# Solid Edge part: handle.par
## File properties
Title: Handle
Author: Robert a Rhodes jr
Template: Normal.par
Last saved by: Cadcim
Revision: 6
Application: Solid Edge
Material: aluminum
Accuracy: 0.99
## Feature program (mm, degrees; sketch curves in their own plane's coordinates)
sketch for "unnamed RevolvedProtrusion 1" plane through (0, 0, 0) normal (0, -1, 0) x-axis (1, 0, 0)
  line (-87.868, 0.2971) -> (-87.868, -4)
  line (-87.868, -4) -> (-79.868, -4)
  line (-79.868, -4) -> (-79.868, -5)
  line (-79.868, -5) -> (76.132, -5)
  line (76.132, -5) -> (76.132, -4)
  line (76.132, -4) -> (84.132, -4)
  line (84.132, -4) -> (84.132, 0.2971)
revolve "unnamed RevolvedProtrusion 1" add finite 360 deg about sketch line (-87.868, 0.2971) -> (84.132, 0.2971)
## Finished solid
Body 1: solid body, 7 faces, 6 edges, 0 vertices.
  Faces by surface: plane 4, cylinder 3
  Edges by curve: circle 6
Bounding box of the edges (mm): 172.000 x 10.594 x 10.594, from (-87.868, -5.2971, -5) to (84.132, 5.2971, 5.5941).
Cylindrical faces by radius (mm): R4.2971 x2, R5.2971 x1
Planar faces by outward normal: +x 2, -x 2
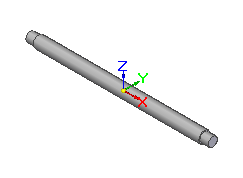
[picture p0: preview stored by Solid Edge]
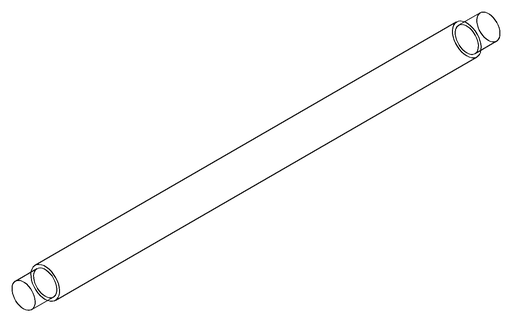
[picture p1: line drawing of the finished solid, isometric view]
